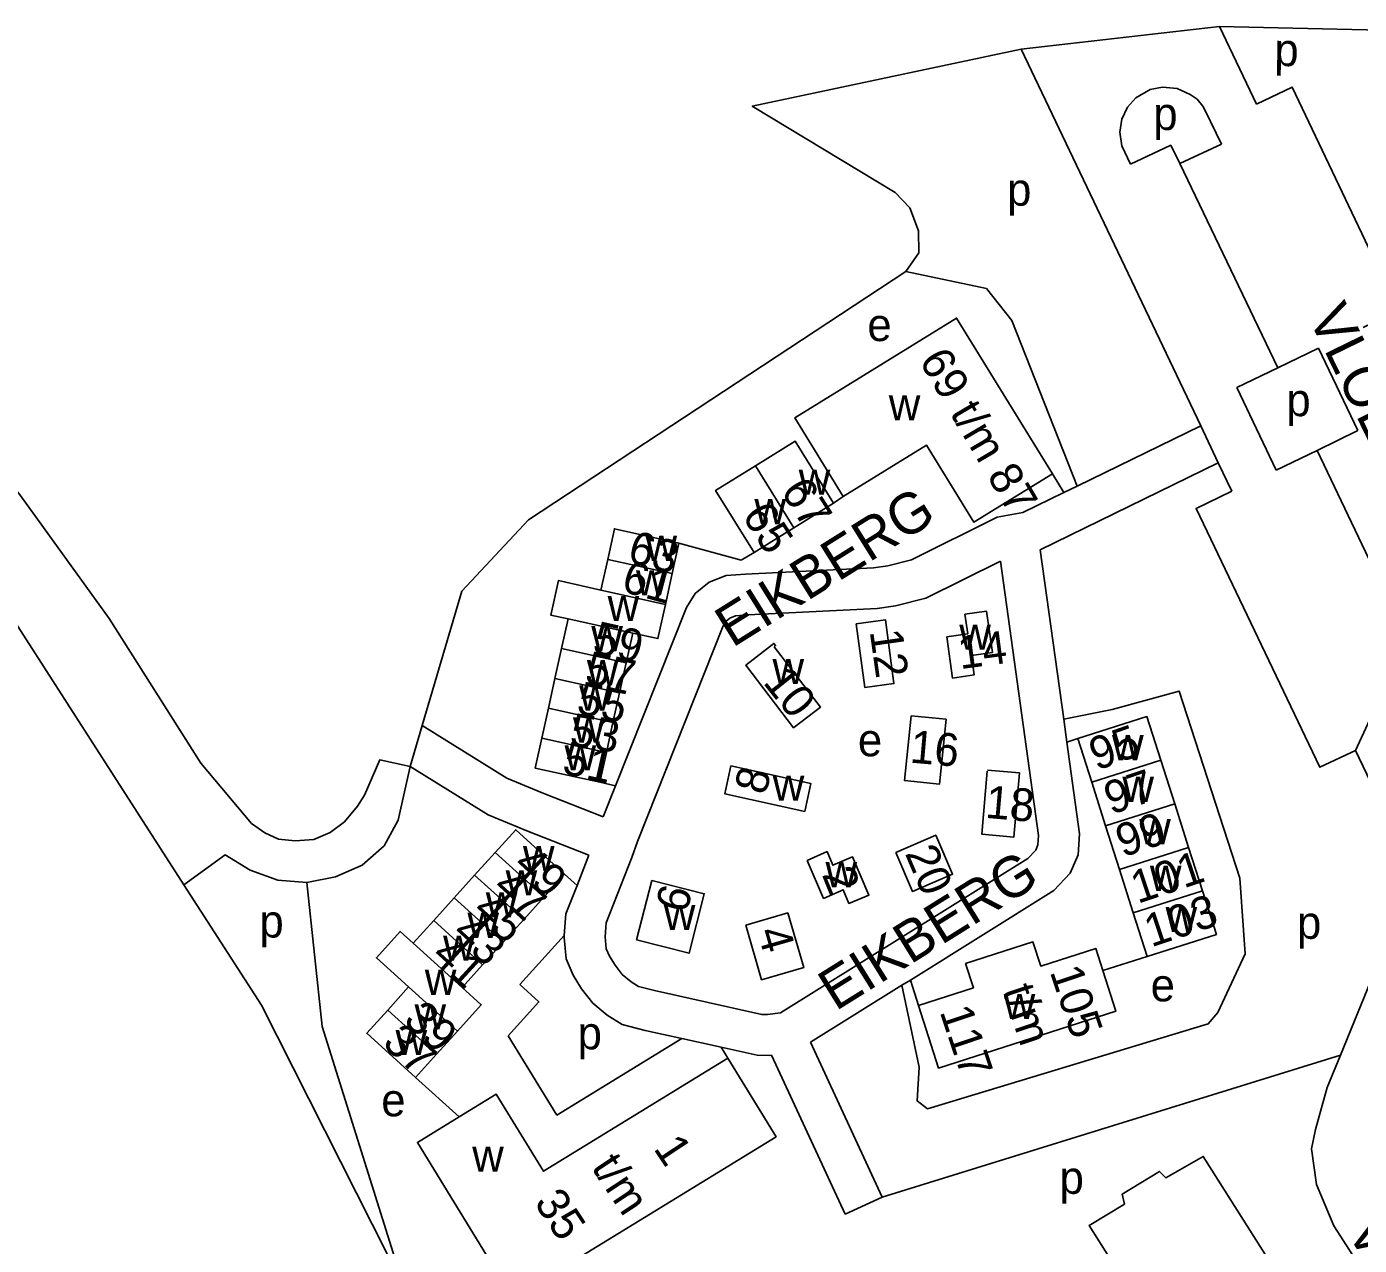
# Model space of a CAD drawing. Extents: x 159441 to 162086, y 388175 to 389787.
# Drawn here: x 159765.8 to 159928.9, y 389394 to 389543.1 of the extents above; entities that cross this region are included whole.
import ezdxf

# ---------------------------------------------------------------- set-up
doc = ezdxf.new("R2010")
doc.units = 0
for name, color, linetype in [('BLT_Basislijn', 7, 'Continuous'), ('BLT_Bebouwing', 7, 'Continuous'), ('BLT_Centroide', 7, 'Continuous'), ('BLT_Huisnummer', 7, 'Continuous'), ('BLT_Huisnummer_reeks', 7, 'Continuous'), ('BLT_Huisnummer_zonder_bebouwing', 7, 'Continuous'), ('BLT_Onderverdeling_panden', 7, 'Continuous'), ('BLT_Plantopo', 7, 'Continuous'), ('BLT_Straatnaam', 7, 'Continuous'), ('BLT_Vlakafsluiter', 7, 'Continuous')]:
    doc.layers.add(name, color=color, linetype=linetype)

msp = doc.modelspace()

# ---------------------------------------------------------------- linework, layer by layer
at = {"layer": 'BLT_Basislijn'}
for p, q in [((159887.47, 389540.32), (159911.75, 389543.06)), ((159911.75, 389543.06), (159916.27, 389533.58)), ((159931.52, 389542.64), (159911.75, 389543.06)), ((159909.44, 389494.22), (159887.47, 389540.32)), ((159906.87, 389526.3), (159911.96, 389528.69)), ((159906.87, 389526.3), (159918.86, 389501.3)), ((159918.86, 389501.3), (159923.86, 389503.72)), ((159923.86, 389503.72), (159928.67, 389493.63)), ((159913.86, 389498.89), (159918.86, 389501.3)), ((159918.68, 389488.79), (159913.86, 389498.89)), ((159894.33, 389486.85), (159909.44, 389494.22)), ((159911.59, 389489.71), (159909.44, 389494.22)), ((159928.67, 389493.63), (159923.68, 389491.21)), ((159923.68, 389491.21), (159918.68, 389488.79)), ((159923.68, 389491.21), (159936.66, 389463.96)), ((159889.78, 389479.07), (159911.59, 389489.71)), ((159913.25, 389486.22), (159911.59, 389489.71)), ((159891.28, 389488.33), (159892.69, 389486.05)), ((159892.69, 389486.05), (159894.33, 389486.85)), ((159864.51, 389484.74), (159865.67, 389485.59)), ((159887.68, 389483.61), (159892.69, 389486.05)), ((159845.58, 389479.88), (159853.2, 389477.77)), ((159854.77, 389478.73), (159853.2, 389477.77)), ((159889.78, 389479.07), (159892.67, 389458.32)), ((159812.69, 389452.56), (159814.16, 389457.54)), ((159892.67, 389458.32), (159893.05, 389455.54)), ((159894.39, 389455.96), (159893.05, 389455.54)), ((159835.89, 389450.62), (159837.83, 389450.19)), ((159837.83, 389450.19), (159836.32, 389446.38)), ((159840.5, 389443.36), (159839.81, 389441.41)), ((159833.11, 389438), (159834.55, 389441.7)), ((159831.59, 389439.38), (159833.11, 389438)), ((159826.12, 389425.86), (159831.55, 389431.88)), ((159902.88, 389429.3), (159897.46, 389427.57)), ((159873.9, 389426.42), (159872.87, 389425.78)), ((159874.9, 389423.3), (159873.9, 389426.42)), ((159872.87, 389425.78), (159861.69, 389418.8)), ((159850.76, 389418.2), (159845.92, 389419.27)), ((159851.58, 389416.87), (159850.76, 389418.2)), ((159861.69, 389418.8), (159870.45, 389399.86)), ((159856.91, 389417.23), (159865.91, 389397.76)), ((159870.45, 389399.86), (159926.53, 389417.24)), ((159813.35, 389414.51), (159818.68, 389409.68)), ((159865.91, 389397.76), (159870.45, 389399.86))]:
    msp.add_line(p, q, dxfattribs=at)
for points in [[(159887.47, 389540.32), (159854.56, 389533.33), (159872.04, 389522.78), (159873.83, 389520.91), (159874.89, 389518.09), (159874.96, 389515.4), (159873.34, 389513.1)], [(159900.83, 389526.23), (159899.77, 389528.46), (159899.53, 389530.14), (159899.8, 389531.75), (159900.49, 389533.19), (159901.49, 389534.35), (159903.27, 389535.36), (159904.75, 389535.64), (159906.57, 389535.49), (159908.13, 389534.77), (159908.99, 389534.17), (159909.68, 389533.33), (159910, 389532.79), (159911.96, 389528.69)], [(159916.27, 389533.58), (159920.64, 389535.64), (159933.64, 389508.34), (159929.3, 389506.26)], [(159900.83, 389526.23), (159905.77, 389528.54), (159906.87, 389526.3)], [(159812.69, 389452.56), (159808.96, 389453.35), (159807.11, 389449.05), (159806.25, 389447.68), (159804.65, 389445.78), (159802.91, 389444.47), (159800.88, 389443.61), (159798.63, 389443.43), (159796.56, 389443.67), (159794.92, 389444.41), (159793.28, 389445.57), (159787.08, 389452.96), (159775.85, 389470.64), (159764.98, 389485.75), (159756.56, 389495.94), (159744.33, 389509.99), (159735.68, 389518.93), (159730.48, 389522.27), (159729.75, 389522.45)], [(159686.19, 389506.58), (159718.3, 389514.83), (159724.87, 389514.38), (159731.69, 389511.48), (159736.57, 389507.05), (159756.38, 389482.5), (159785, 389438.06)], [(159873.34, 389513.1), (159827.18, 389482.73), (159819, 389474), (159814.16, 389457.54)], [(159873.34, 389513.1), (159883.21, 389511.02), (159886.31, 389507.09), (159894.33, 389486.85)], [(159913.25, 389486.22), (159908.86, 389484.11), (159924.01, 389452.45), (159928.38, 389454.5)], [(159887.68, 389483.61), (159884.51, 389483.03), (159874.04, 389477.84), (159871.13, 389477.1), (159869.38, 389476.86), (159853.74, 389476.09), (159851.38, 389475.91), (159849.29, 389475.08), (159847.56, 389473.7), (159846.51, 389471.99), (159837.83, 389450.19)], [(159884.93, 389477.66), (159875.78, 389473.12), (159872.08, 389472.19), (159869.85, 389471.88), (159854.06, 389471.1), (159852.52, 389470.98), (159851.82, 389470.7), (159851.36, 389470.34), (159850.99, 389469.74), (159840.5, 389443.36)], [(159884.93, 389477.66), (159889.6, 389444.11), (159889.52, 389442.94), (159889.25, 389442.3), (159888.28, 389441.29), (159858.01, 389422.4)], [(159872.87, 389425.78), (159875, 389415.75), (159874.72, 389411.63), (159875.99, 389410.65), (159910.35, 389421.08), (159911.55, 389422.45), (159914.89, 389429.62), (159914.21, 389438.88), (159906.79, 389461.77), (159898.6, 389459.51), (159892.67, 389458.32)], [(159836.32, 389446.38), (159828.84, 389449.32), (159824.5, 389451.1), (159814.16, 389457.54)], [(159893.05, 389455.54), (159894.62, 389444.29), (159894.45, 389441.75), (159893.48, 389439.5), (159891.46, 389437.38), (159873.9, 389426.42)], [(159928.38, 389454.5), (159934.47, 389441.81), (159934.95, 389439.98), (159934.88, 389437.98), (159933.62, 389434.51), (159926.53, 389417.24)], [(159812.69, 389452.56), (159811.22, 389445.98), (159809.51, 389442.84), (159806.81, 389440.49), (159803.55, 389439.03), (159800.04, 389438.34)], [(159834.55, 389441.7), (159826.98, 389444.68), (159822.22, 389446.63), (159812.69, 389452.56)], [(159800.04, 389438.34), (159796.48, 389438.64), (159793.11, 389439.85), (159790.06, 389441.72), (159785, 389438.06)], [(159858.01, 389422.4), (159856.43, 389422.21), (159855.74, 389422.22), (159842.61, 389425.12), (159840.63, 389425.62), (159839.74, 389426.18), (159838.64, 389427.1), (159837.76, 389428.23), (159837.08, 389429.32), (159836.69, 389430.24), (159836.55, 389431.69), (159836.68, 389433.4), (159839.81, 389441.41)], [(159785, 389438.06), (159794.48, 389423.34), (159811.91, 389388.9)], [(159800.04, 389438.34), (159801.93, 389420.75), (159811.91, 389388.9)], [(159831.55, 389431.88), (159831.75, 389434.52), (159833.11, 389438)], [(159845.92, 389419.27), (159841.46, 389420.26), (159838.64, 389420.97), (159836.79, 389422.13), (159835.03, 389423.6), (159833.66, 389425.36), (159832.62, 389427.02), (159831.79, 389429), (159831.53, 389431.64), (159831.55, 389431.88)], [(159826.12, 389425.86), (159828.45, 389423.75), (159824.68, 389419.58)], [(159845.92, 389419.27), (159830.65, 389409.9), (159824.68, 389419.58)], [(159856.91, 389417.23), (159856.69, 389417.2), (159855.14, 389417.23), (159850.76, 389418.2)], [(159926.53, 389417.24), (159924.9, 389413.28), (159923.5, 389408.14), (159922.98, 389405.75), (159923.61, 389401.39), (159925.74, 389396.35), (159939.01, 389375.68)], [(159900.1, 389399), (159899.81, 389400.22), (159904.39, 389403.01), (159905.17, 389402.21), (159909.74, 389404.85), (159928.63, 389375.01), (159924.37, 389372.26), (159926.89, 389367.85)], [(159900.1, 389399), (159895.77, 389396.37), (159914.73, 389366.4), (159919.08, 389369.06), (159921.66, 389364.95)]]:
    msp.add_lwpolyline(points, dxfattribs=at)
at = {"layer": 'BLT_Bebouwing'}
for p, q in [((159864.51, 389484.74), (159859.64, 389481.74)), ((159859.64, 389481.74), (159854.77, 389478.73)), ((159844.76, 389476.14), (159845.58, 389479.88)), ((159836.86, 389477.88), (159836.03, 389474.13)), ((159843.92, 389472.38), (159844.76, 389476.14)), ((159832.02, 389470.6), (159831.22, 389466.97)), ((159839.12, 389465.22), (159839.93, 389468.87)), ((159831.22, 389466.97), (159830.41, 389463.32)), ((159838.31, 389461.57), (159839.12, 389465.22)), ((159830.41, 389463.32), (159829.6, 389459.67)), ((159837.51, 389457.92), (159838.31, 389461.57)), ((159829.6, 389459.67), (159828.8, 389456.02)), ((159836.7, 389454.27), (159837.51, 389457.92)), ((159894.39, 389455.96), (159896.1, 389450.61)), ((159835.89, 389450.62), (159836.7, 389454.27)), ((159906.25, 389447.98), (159904.56, 389453.31)), ((159896.1, 389450.61), (159897.79, 389445.29)), ((159907.95, 389442.65), (159906.25, 389447.98)), ((159897.79, 389445.29), (159899.49, 389439.96)), ((159909.65, 389437.33), (159907.95, 389442.65)), ((159823.08, 389442.02), (159820.58, 389439.25)), ((159820.58, 389439.25), (159818.08, 389436.47)), ((159829.08, 389436.6), (159831.59, 389439.38)), ((159899.49, 389439.96), (159901.19, 389434.63)), ((159818.08, 389436.47), (159815.57, 389433.7)), ((159826.58, 389433.83), (159829.08, 389436.6)), ((159901.19, 389434.63), (159902.88, 389429.3)), ((159815.57, 389433.7), (159813.06, 389430.92)), ((159824.07, 389431.06), (159826.58, 389433.83)), ((159821.56, 389428.28), (159824.07, 389431.06)), ((159819.06, 389425.51), (159821.56, 389428.28)), ((159812.5, 389425.58), (159809.94, 389422.74)), ((159815.91, 389417.35), (159818.48, 389420.18)), ((159813.35, 389414.51), (159815.91, 389417.35))]:
    msp.add_line(p, q, dxfattribs=at)
for points in [[(159865.67, 389485.59), (159859.75, 389495.18), (159879.55, 389507.41), (159891.28, 389488.33)], [(159854.95, 389489.33), (159859.82, 389492.33), (159864.51, 389484.74)], [(159891.28, 389488.33), (159881.68, 389482.43), (159875.86, 389491.86), (159865.67, 389485.59)], [(159854.77, 389478.73), (159850.07, 389486.32), (159854.95, 389489.33)], [(159845.58, 389479.88), (159837.68, 389481.63), (159836.86, 389477.88)], [(159836.03, 389474.13), (159830.84, 389475.29), (159829.9, 389471.07), (159832.02, 389470.6)], [(159839.93, 389468.87), (159843, 389468.19), (159843.92, 389472.38)], [(159904.56, 389453.31), (159902.86, 389458.64), (159894.39, 389455.96)], [(159828.8, 389456.02), (159827.99, 389452.35), (159835.89, 389450.62)], [(159831.59, 389439.38), (159825.6, 389444.8), (159823.08, 389442.02)], [(159902.88, 389429.3), (159911.35, 389432), (159909.65, 389437.33)], [(159813.06, 389430.92), (159811.46, 389432.36), (159808.56, 389429.15), (159812.5, 389425.58)], [(159897.46, 389427.57), (159896.59, 389430.28), (159889.86, 389428.12), (159888.91, 389431.09), (159880.66, 389428.43), (159881.62, 389425.47), (159874.9, 389423.3)], [(159874.9, 389423.3), (159877.36, 389415.64), (159899.04, 389422.61), (159897.46, 389427.57)], [(159818.48, 389420.18), (159821.39, 389423.4), (159819.06, 389425.51)], [(159809.94, 389422.74), (159807.38, 389419.91), (159813.35, 389414.51)], [(159818.68, 389409.68), (159823.2, 389412.46), (159829.02, 389403.03), (159851.58, 389416.87)], [(159851.58, 389416.87), (159857.47, 389407.24), (159825.27, 389387.48)], [(159825.27, 389387.48), (159813.58, 389406.55), (159818.68, 389409.68)]]:
    msp.add_lwpolyline(points, dxfattribs=at)
for points in [[(159878.35, 389468.4), (159880.93, 389468.79), (159880.58, 389471.16), (159883.24, 389471.53), (159883.95, 389466.5), (159881.37, 389466.13), (159881.73, 389463.76), (159879.08, 389463.37)], [(159857.24, 389467.2), (159862.92, 389459.82), (159859.8, 389457.42), (159859.62, 389457.28), (159853.76, 389464.94), (159857.21, 389467.6), (159857.41, 389467.33)], [(159851.95, 389452.61), (159861.72, 389450.48), (159860.97, 389447.05), (159851.2, 389449.19)], [(159861.27, 389441.06), (159863.72, 389442.13), (159864.42, 389440.47), (159866.82, 389441.5), (159868.83, 389436.82), (159866.38, 389435.79), (159865.68, 389437.46), (159863.28, 389436.41)], [(159842.26, 389438.61), (159848.68, 389436.98), (159846.82, 389429.69), (159840.4, 389431.32)]]:
    msp.add_lwpolyline(points, close=True, dxfattribs=at)
at = {"layer": 'BLT_Onderverdeling_panden'}
for p, q in [((159854.95, 389489.33), (159859.64, 389481.74)), ((159836.86, 389477.88), (159844.76, 389476.14)), ((159843.92, 389472.38), (159836.03, 389474.13)), ((159832.02, 389470.6), (159839.93, 389468.87)), ((159839.12, 389465.22), (159831.22, 389466.97)), ((159830.41, 389463.32), (159838.31, 389461.57)), ((159829.6, 389459.67), (159837.51, 389457.92)), ((159828.8, 389456.02), (159836.7, 389454.27)), ((159896.1, 389450.61), (159904.56, 389453.31)), ((159897.79, 389445.29), (159906.25, 389447.98)), ((159907.95, 389442.65), (159899.49, 389439.96)), ((159823.08, 389442.02), (159829.08, 389436.6)), ((159820.58, 389439.25), (159826.58, 389433.83)), ((159901.19, 389434.63), (159909.65, 389437.33)), ((159818.08, 389436.47), (159824.07, 389431.06)), ((159815.57, 389433.7), (159821.56, 389428.28)), ((159813.06, 389430.92), (159819.06, 389425.51)), ((159812.5, 389425.58), (159818.48, 389420.18)), ((159809.94, 389422.74), (159815.91, 389417.35))]:
    msp.add_line(p, q, dxfattribs=at)
at = {"layer": 'BLT_Plantopo'}
for points in [[(159867.29, 389470), (159870.88, 389470.47), (159871.9, 389462.68), (159868.32, 389462.21)], [(159873.99, 389458.76), (159878.27, 389458.33), (159877.47, 389450.4), (159873.18, 389450.84)], [(159872.11, 389442.04), (159877.02, 389444.16), (159879.08, 389439.38), (159874.16, 389437.26)], [(159853.75, 389433.14), (159858.89, 389434.64), (159860.85, 389427.95), (159855.7, 389426.45)]]:
    msp.add_lwpolyline(points, close=True, dxfattribs=at)
msp.add_lwpolyline([(159883.34, 389452.1), (159887.26, 389451.75), (159886.57, 389443.9), (159882.65, 389444.25), (159883.32, 389451.98)], dxfattribs=at)
at = {"layer": 'BLT_Vlakafsluiter'}
msp.add_line((159928.38, 389454.5), (159931.65, 389461.56), dxfattribs=at)

# ---------------------------------------------------------------- texts
at = {"layer": 'BLT_Centroide'}
msp.add_text('p', height=4, rotation=359, dxfattribs=at).set_placement((159918.42, 389538.26))
for s, p in [('p', (159903.63, 389530.41)), ('p', (159885.74, 389521.15)), ('e', (159868.64, 389504.59)), ('w', (159871.26, 389494.88)), ('p', (159919.92, 389495.4)), ('w', (159860.24, 389485.78)), ('w', (159854.82, 389482.19)), ('w', (159841.49, 389477.7)), ('w', (159840.32, 389473.47)), ('w', (159836.85, 389470.34)), ('w', (159879.89, 389466.82)), ('w', (159834.86, 389466.64)), ('w', (159834.32, 389462.49)), ('w', (159857.03, 389462.62)), ('w', (159833.38, 389459.39)), ('w', (159832.62, 389455.47)), ('e', (159867.48, 389453.8)), ('w', (159898.59, 389453.31)), ('w', (159831.58, 389452.06)), ('w', (159857.06, 389448.35)), ('w', (159899.85, 389448.22)), ('w', (159901.91, 389443.04)), ('w', (159826.49, 389439.74)), ('w', (159863.52, 389437.78)), ('w', (159824.37, 389436.77)), ('w', (159903.22, 389437.32)), ('w', (159821.94, 389434.08)), ('w', (159843.73, 389432.54)), ('p', (159794.24, 389431.62)), ('w', (159819.7, 389431.58)), ('w', (159905.13, 389432.29)), ('p', (159921.22, 389431.46)), ('w', (159816.72, 389428.77)), ('w', (159814.48, 389424.6)), ('e', (159903.31, 389423.81)), ('w', (159885.33, 389421.65)), ('w', (159813.22, 389420.39)), ('p', (159833.18, 389417.94)), ('w', (159810.9, 389417.23)), ('e', (159809.15, 389409.75)), ('w', (159820.28, 389402.97)), ('p', (159892.16, 389400.26))]:
    msp.add_text(s, height=4, dxfattribs=at).set_placement(p)
at = {"layer": 'BLT_Huisnummer'}
for s, rotation, p in [('67', 302.5267, (159857.96, 389486.23)), ('65', 302.5267, (159853.22, 389483.23)), ('63', 344.5267, (159839.13, 389477.64)), ('61', 344.5267, (159838.4, 389474.01)), ('59', 347.5267, (159834.86, 389466.45)), ('14', 7.5267, (159880, 389464.45)), ('57', 347.5267, (159833.91, 389462.8)), ('10', 308.5267, (159855.77, 389462.81)), ('55', 347.5267, (159832.9, 389459.09)), ('53', 350.5267, (159832.08, 389455.17)), ('95', 19.5267, (159896.68, 389452.01)), ('51', 347.5267, (159831.14, 389451.73)), ('8', 74.5267, (159856.14, 389448.93)), ('97', 18.5267, (159898.45, 389446.62)), ('99', 18.5267, (159899.88, 389441.4)), ('49', 317.5267, (159825.12, 389440.25)), ('101', 18.5267, (159901.72, 389435.73)), ('47', 317.5267, (159822.61, 389437.5)), ('2', 292.0267, (159863.04, 389439.34)), ('6', 74.5267, (159846.49, 389434.47)), ('45', 317.5267, (159820.14, 389434.68)), ('103', 18.5267, (159903.37, 389430.4)), ('43', 317.5267, (159817.65, 389431.92)), ('41', 317.5267, (159815.11, 389429.17)), ('39', 317.5267, (159811.71, 389421.28)), ('37', 317.5267, (159809.14, 389418.49))]:
    msp.add_text(s, height=4, rotation=rotation, dxfattribs=at).set_placement(p)
at = {"layer": 'BLT_Huisnummer_reeks'}
for s, rotation, p in [('69 t/m 87', 300.5267, (159874.9, 389502.21)), ('105', 288.5267, (159890.94, 389427.46)), ('t/m', 288.5267, (159885.13, 389425.15)), ('117', 288.5267, (159877.46, 389422.57)), ('1', 303.5267, (159842.4, 389405.81)), ('t/m', 303.5267, (159834.78, 389403.51)), ('35', 303.5267, (159827.78, 389399.18))]:
    msp.add_text(s, height=4, rotation=rotation, dxfattribs=at).set_placement(p)
at = {"layer": 'BLT_Huisnummer_zonder_bebouwing'}
for s, rotation, p in [('12', 278.0267, (159868.92, 389469.09)), ('16', 355.0267, (159873.75, 389453.03)), ('18', 355.0267, (159882.98, 389446.27)), ('20', 293.0267, (159873.2, 389441.93)), ('4', 286.0267, (159855.16, 389432.35))]:
    msp.add_text(s, height=4, rotation=rotation, dxfattribs=at).set_placement(p)
at = {"layer": 'BLT_Straatnaam'}
for s, rotation, p in [('VLOET', 296.0004, (159922.51, 389507.59)), ('EIKBERG', 32.0004, (159852.12, 389467.02)), ('EIKBERG', 32.0004, (159864.76, 389422.56)), ('VLOET', 302.0004, (159927.19, 389395.65))]:
    msp.add_text(s, height=5, rotation=rotation, dxfattribs=at).set_placement(p)

doc.saveas('drawing.dxf')
